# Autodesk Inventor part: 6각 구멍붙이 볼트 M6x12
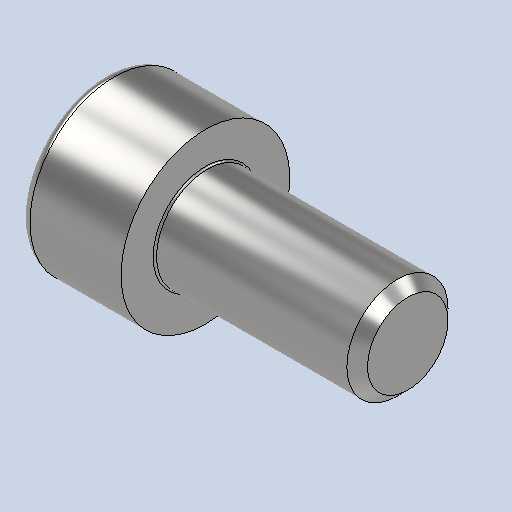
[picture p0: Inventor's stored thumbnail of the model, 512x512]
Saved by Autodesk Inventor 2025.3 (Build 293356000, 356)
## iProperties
Created: 2026-01
Part Number: 6각 구멍붙이 볼트 M6x12
Material: 강철, 연강
Description: 6각머리 태핑 나사
Document SubType Name: Modeling
Designer: pc6
Density: 7.85 g/cm^3
Appearance: 기본값
Author: jhkim
Sending System: Autodesk Inventor 2026
Preprocessor: ST-DEVELOPER v20.1
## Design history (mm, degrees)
feature "Solid1"
node "솔리드1"
